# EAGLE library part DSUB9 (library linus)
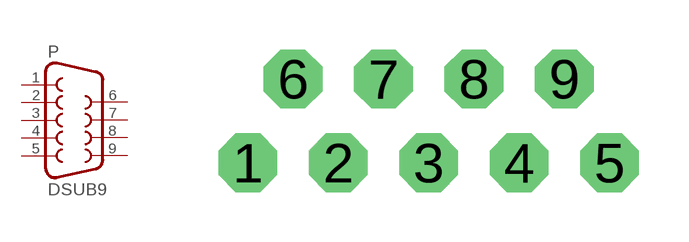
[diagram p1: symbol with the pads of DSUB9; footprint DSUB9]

Designator prefix P

## DSUB9  [DSUB9]
1  1  pas
2  2  pas
3  3  pas
4  4  pas
5  5  pas
6  6  pas
7  7  pas
8  8  pas
9  9  pas

## Footprint DSUB9 (pad centres in mm)
drill 1.016 pad 1.778 octagon: 1 -5.486,-1.27; 2 -2.743,-1.27; 3 0,-1.27; 4 2.743,-1.27; 5 5.486,-1.27; 6 -4.115,1.27; 7 -1.372,1.27; 8 1.372,1.27; 9 4.115,1.27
